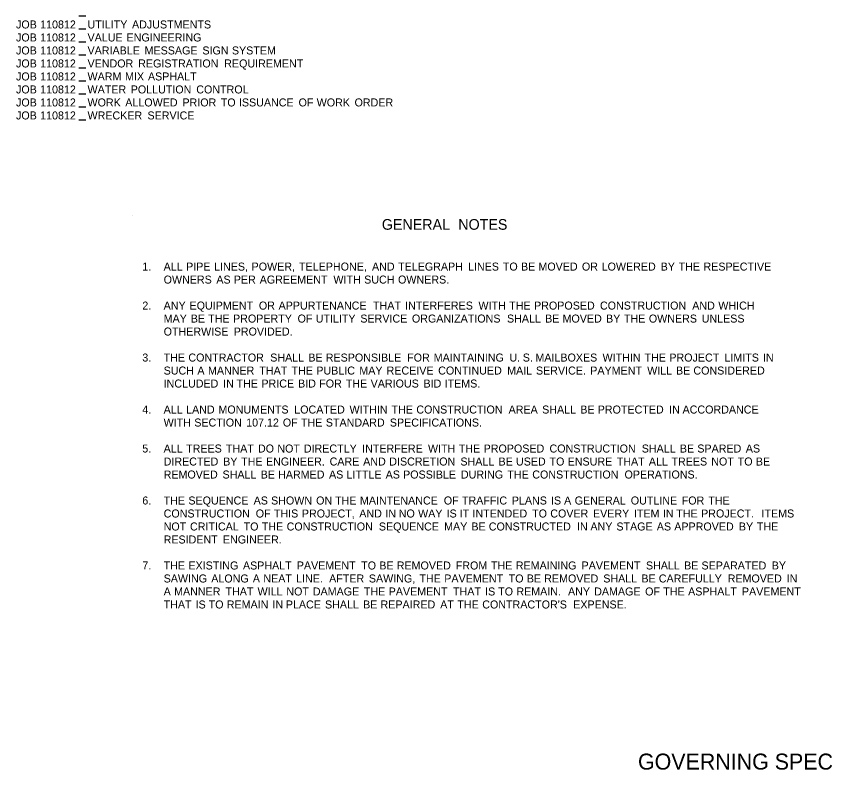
# Model space of a CAD drawing. Extents: x 200 to 2094, y 35 to 1167.
# Drawn here: x 768 to 1375, y 35 to 600 of the extents above; entities that cross this region are included whole.
import ezdxf

# ---------------------------------------------------------------- set-up
doc = ezdxf.new("R2010")
doc.units = 0
doc.layers.add('Default', color=7, linetype='Continuous')
doc.layers.add('R_Annotation', color=7, linetype='Continuous')

msp = doc.modelspace()

# ---------------------------------------------------------------- linework, layer by layer
at = {"layer": 'Default'}
for p, q in [((820.04, 600.08), (814.8, 600.08)), ((820.04, 590.33), (814.8, 590.33)), ((820.04, 580.58), (814.8, 580.58)), ((820.04, 570.83), (814.8, 570.83)), ((820.04, 561.08), (814.8, 561.08)), ((820.04, 551.33), (814.8, 551.33)), ((820.04, 541.58), (814.8, 541.58)), ((820.04, 531.83), (814.8, 531.83)), ((820.04, 522.08), (814.8, 522.08)), ((855.05, 450.43), (855.05, 450.43))]:
    msp.add_line(p, q, dxfattribs=at)

# ---------------------------------------------------------------- texts
for s, height, p in [('JOB', 6, (767.74, 590.87)), (' 110812', 6, (783.6, 590.87)), ('UTILITY', 6, (821.37, 590.87)), (' ADJUSTMENTS', 6, (852.51, 590.87)), ('JOB', 6, (767.74, 581.12)), (' 110812', 6, (783.6, 581.12)), ('VALUE', 6, (821.37, 581.12)), (' ENGINEERING', 6, (848.42, 581.12)), ('JOB', 6, (767.74, 571.37)), (' 110812', 6, (783.6, 571.37)), ('VARIABLE', 6, (821.37, 571.37)), (' MESSAGE', 6, (861.93, 571.37)), (' SIGN', 6, (905.28, 571.37)), (' SYSTEM', 6, (927.42, 571.37)), ('JOB', 6, (767.74, 561.62)), (' 110812', 6, (783.6, 561.62)), ('VENDOR', 6, (821.37, 561.62)), (' REGISTRATION', 6, (857.13, 561.62)), (' REQUIREMENT', 6, (921.65, 561.62)), ('JOB', 6, (767.74, 551.87)), (' 110812', 6, (783.6, 551.87)), ('WARM', 6, (821.37, 551.87)), (' MIX', 6, (847.28, 551.87)), (' ASPHALT', 6, (864.46, 551.87)), ('JOB', 6, (767.74, 542.12)), (' 110812', 6, (783.6, 542.12)), ('WATER', 6, (821.37, 542.12)), (' POLLUTION', 6, (851.53, 542.12)), (' CONTROL', 6, (900.69, 542.12)), ('JOB', 6, (767.74, 532.37)), (' 110812', 6, (783.6, 532.37)), ('WORK', 6, (821.37, 532.37)), (' ALLOWED', 6, (847.43, 532.37)), (' PRIOR', 6, (890.31, 532.37)), (' TO', 6, (919.07, 532.37)), (' ISSUANCE', 6, (932.67, 532.37)), (' OF', 6, (977.41, 532.37)), (' WORK', 6, (991, 532.37)), (' ORDER', 6, (1019.39, 532.37)), ('JOB', 6, (767.74, 522.62)), (' 110812', 6, (783.6, 522.62)), ('WRECKER', 6, (821.37, 522.62)), (' SERVICE', 6, (864.11, 522.62)), ('GENERAL', 8, (1042.08, 439.85)), (' NOTES', 8, (1096.41, 439.85)), ('1.', 6, (862.44, 409.22)), ('ALL', 6, (878.45, 409.22)), (' PIPE', 6, (893.06, 409.22)), (' LINES,', 6, (914.05, 409.22)), (' POWER,', 6, (942.19, 409.22)), (' TELEPHONE,', 6, (977.77, 409.22)), (' AND', 6, (1032.47, 409.22)), (' TELEGRAPH', 6, (1052.05, 409.22)), (' LINES', 6, (1104.49, 409.22)), (' TO', 6, (1130.6, 409.22)), (' BE', 6, (1144.2, 409.22)), (' MOVED', 6, (1157.27, 409.22)), (' OR', 6, (1189.89, 409.22)), (' LOWERED', 6, (1204.68, 409.22)), (' BY', 6, (1248.95, 409.22)), (' THE', 6, (1262.4, 409.22)), (' RESPECTIVE', 6, (1281.05, 409.22)), ('OWNERS', 6, (878.45, 399.47)), (' AS', 6, (915.74, 399.47)), (' PER', 6, (928.81, 399.47)), (' AGREEMENT', 6, (948.27, 399.47)), (' WITH', 6, (1003.53, 399.47)), (' SUCH', 6, (1026.6, 399.47)), (' OWNERS.', 6, (1052.01, 399.47)), ('2.', 6, (862.44, 379.97)), ('ANY', 6, (878.45, 379.97)), (' EQUIPMENT', 6, (895.63, 379.97)), (' OR', 6, (947.63, 379.97)), (' APPURTENANCE', 6, (962.42, 379.97)), (' THAT', 6, (1033.25, 379.97)), (' INTERFERES', 6, (1057.3, 379.97)), (' WITH', 6, (1112.3, 379.97)), (' THE', 6, (1135.36, 379.97)), (' PROPOSED', 6, (1154.01, 379.97)), (' CONSTRUCTION', 6, (1203.42, 379.97)), (' AND', 6, (1272.6, 379.97)), (' WHICH', 6, (1292.18, 379.97)), ('MAY', 6, (878.45, 370.22)), (' BE', 6, (896.55, 370.22)), (' THE', 6, (909.62, 370.22)), (' PROPERTY', 6, (928.27, 370.22)), (' OF', 6, (976.66, 370.22)), (' UTILITY', 6, (990.24, 370.22)), (' SERVICE', 6, (1023.72, 370.22)), (' ORGANIZATIONS', 6, (1062.4, 370.22)), (' SHALL', 6, (1133.7, 370.22)), (' BE', 6, (1162.29, 370.22)), (' MOVED', 6, (1175.36, 370.22)), (' BY', 6, (1207.98, 370.22)), (' THE', 6, (1221.43, 370.22)), (' OWNERS', 6, (1240.08, 370.22)), (' UNLESS', 6, (1279.7, 370.22)), ('OTHERWISE', 6, (878.45, 360.47)), (' PROVIDED.', 6, (928.77, 360.47)), ('3.', 6, (862.44, 340.97)), ('THE', 6, (878.45, 340.97)), (' CONTRACTOR', 6, (894.77, 340.97)), (' SHALL', 6, (956.14, 340.97)), (' BE', 6, (984.73, 340.97)), (' RESPONSIBLE', 6, (997.79, 340.97)), (' FOR', 6, (1058.85, 340.97)), (' MAINTAINING', 6, (1078.76, 340.97)), (' U.', 6, (1135.53, 340.97)), (' S.', 6, (1145.5, 340.97)), (' MAILBOXES', 6, (1155.02, 340.97)), (' WITHIN', 6, (1205.37, 340.97)), (' THE', 6, (1236.81, 340.97)), (' PROJECT', 6, (1255.46, 340.97)), (' LIMITS', 6, (1296.75, 340.97)), (' IN', 6, (1325.65, 340.97)), ('SUCH', 6, (878.45, 331.22)), (' A', 6, (901.53, 331.22)), (' MANNER', 6, (909.46, 331.22)), (' THAT', 6, (948.01, 331.22)), (' THE', 6, (972.06, 331.22)), (' PUBLIC', 6, (990.71, 331.22)), (' MAY', 6, (1022.99, 331.22)), (' RECEIVE', 6, (1043.42, 331.22)), (' CONTINUED', 6, (1082.11, 331.22)), (' MAIL', 6, (1133.83, 331.22)), (' SERVICE.', 6, (1155.42, 331.22)), (' PAYMENT', 6, (1196.16, 331.22)), (' WILL', 6, (1238.85, 331.22)), (' BE', 6, (1260.44, 331.22)), (' CONSIDERED', 6, (1273.5, 331.22)), ('INCLUDED', 6, (878.45, 321.47)), (' IN', 6, (920.86, 321.47)), (' THE', 6, (930.88, 321.47)), (' PRICE', 6, (949.53, 321.47)), (' BID', 6, (977.03, 321.47)), (' FOR', 6, (992.89, 321.47)), (' THE', 6, (1012.8, 321.47)), (' VARIOUS', 6, (1031.45, 321.47)), (' BID', 6, (1071.08, 321.47)), (' ITEMS.', 6, (1086.93, 321.47)), ('4.', 6, (862.44, 301.97)), ('ALL', 6, (878.45, 301.97)), (' LAND', 6, (893.06, 301.97)), (' MONUMENTS', 6, (917.31, 301.97)), (' LOCATED', 6, (974.16, 301.97)), (' WITHIN', 6, (1015.63, 301.97)), (' THE', 6, (1047.08, 301.97)), (' CONSTRUCTION', 6, (1065.72, 301.97)), (' AREA', 6, (1134.9, 301.97)), (' SHALL', 6, (1160.08, 301.97)), (' BE', 6, (1188.67, 301.97)), (' PROTECTED', 6, (1201.74, 301.97)), (' IN', 6, (1255.32, 301.97)), (' ACCORDANCE', 6, (1265.35, 301.97)), ('WITH', 6, (878.45, 292.22)), (' SECTION', 6, (899.19, 292.22)), (' 107.12', 6, (938.1, 292.22)), (' OF', 6, (965.61, 292.22)), (' THE', 6, (979.2, 292.22)), (' STANDARD', 6, (997.85, 292.22)), (' SPECIFICATIONS.', 6, (1045.85, 292.22)), ('5.', 6, (862.44, 272.72)), ('ALL', 6, (878.45, 272.72)), (' TREES', 6, (893.06, 272.72)), (' THAT', 6, (922.91, 272.72)), (' DO', 6, (946.96, 272.72)), (' NOT', 6, (961.49, 272.72)), (' DIRECTLY', 6, (981.35, 272.72)), (' INTERFERE', 6, (1025.07, 272.72)), (' WITH', 6, (1074.46, 272.72)), (' THE', 6, (1097.53, 272.72)), (' PROPOSED', 6, (1116.18, 272.72)), (' CONSTRUCTION', 6, (1165.58, 272.72)), (' SHALL', 6, (1234.76, 272.72)), (' BE', 6, (1263.35, 272.72)), (' SPARED', 6, (1276.42, 272.72)), (' AS', 6, (1312.78, 272.72)), ('DIRECTED', 6, (878.45, 262.97)), (' BY', 6, (920.86, 262.97)), (' THE', 6, (934.31, 262.97)), (' ENGINEER.', 6, (952.95, 262.97)), (' CARE', 6, (1000.67, 262.97)), (' AND', 6, (1025.85, 262.97)), (' DISCRETION', 6, (1045.43, 262.97)), (' SHALL', 6, (1098.78, 262.97)), (' BE', 6, (1127.37, 262.97)), (' USED', 6, (1140.43, 262.97)), (' TO', 6, (1165.61, 262.97)), (' ENSURE', 6, (1179.2, 262.97)), (' THAT', 6, (1216.03, 262.97)), (' ALL', 6, (1240.08, 262.97)), (' TREES', 6, (1257.02, 262.97)), (' NOT', 6, (1286.86, 262.97)), (' TO', 6, (1306.72, 262.97)), (' BE', 6, (1320.32, 262.97)), ('REMOVED', 6, (878.45, 253.22)), (' SHALL', 6, (920.39, 253.22)), (' BE', 6, (948.99, 253.22)), (' HARMED', 6, (962.05, 253.22)), (' AS', 6, (1000.26, 253.22)), (' LITTLE', 6, (1013.34, 253.22)), (' AS', 6, (1042.7, 253.22)), (' POSSIBLE', 6, (1055.78, 253.22)), (' DURING', 6, (1099.13, 253.22)), (' THE', 6, (1134, 253.22)), (' CONSTRUCTION', 6, (1152.65, 253.22)), (' OPERATIONS.', 6, (1221.83, 253.22)), ('6.', 6, (862.44, 233.72)), ('THE', 6, (878.45, 233.72)), (' SEQUENCE', 6, (894.77, 233.72)), (' AS', 6, (943.71, 233.72)), (' SHOWN', 6, (956.78, 233.72)), (' ON', 6, (990.56, 233.72)), (' THE', 6, (1004.78, 233.72)), (' MAINTENANCE', 6, (1023.43, 233.72)), (' OF', 6, (1086.33, 233.72)), (' TRAFFIC', 6, (1099.92, 233.72)), (' PLANS', 6, (1137.31, 233.72)), (' IS', 6, (1166.69, 233.72)), (' A', 6, (1176.5, 233.72)), (' GENERAL', 6, (1184.44, 233.72)), (' OUTLINE', 6, (1226.54, 233.72)), (' FOR', 6, (1264.75, 233.72)), (' THE', 6, (1284.66, 233.72)), ('CONSTRUCTION', 6, (878.45, 223.97)), (' OF', 6, (945.3, 223.97)), (' THIS', 6, (958.89, 223.97)), (' PROJECT,', 6, (979.87, 223.97)), (' AND', 6, (1022.92, 223.97)), (' IN', 6, (1042.5, 223.97)), (' NO', 6, (1052.52, 223.97)), (' WAY', 6, (1067.05, 223.97)), (' IS', 6, (1088.41, 223.97)), (' IT', 6, (1098.22, 223.97)), (' INTENDED', 6, (1107.83, 223.97)), (' TO', 6, (1152.56, 223.97)), (' COVER', 6, (1166.16, 223.97)), (' EVERY', 6, (1198.19, 223.97)), (' ITEM', 6, (1228.88, 223.97)), (' IN', 6, (1250.6, 223.97)), (' THE', 6, (1260.63, 223.97)), (' PROJECT.', 6, (1279.28, 223.97)), ('  ITEMS', 6, (1322.33, 223.97)), ('NOT', 6, (878.45, 214.22)), (' CRITICAL', 6, (895.98, 214.22)), (' TO', 6, (936.2, 214.22)), (' THE', 6, (949.8, 214.22)), (' CONSTRUCTION', 6, (968.45, 214.22)), (' SEQUENCE', 6, (1037.63, 214.22)), (' MAY', 6, (1086.56, 214.22)), (' BE', 6, (1107, 214.22)), (' CONSTRUCTED', 6, (1120.06, 214.22)), (' IN', 6, (1186.22, 214.22)), (' ANY', 6, (1196.25, 214.22)), (' STAGE', 6, (1215.75, 214.22)), (' AS', 6, (1246.05, 214.22)), (' APPROVED', 6, (1259.13, 214.22)), (' BY', 6, (1307.6, 214.22)), (' THE', 6, (1321.05, 214.22)), ('RESIDENT', 6, (878.45, 204.47)), (' ENGINEER.', 6, (920.67, 204.47)), ('7.', 6, (862.44, 184.97)), ('THE', 6, (878.45, 184.97)), (' EXISTING', 6, (894.77, 184.97)), (' ASPHALT', 6, (935.7, 184.97)), (' PAVEMENT', 6, (976.07, 184.97)), (' TO', 6, (1024.36, 184.97)), (' BE', 6, (1037.95, 184.97)), (' REMOVED', 6, (1051.02, 184.97)), (' FROM', 6, (1095.29, 184.97)), (' THE', 6, (1121.67, 184.97)), (' REMAINING', 6, (1140.32, 184.97)), (' PAVEMENT', 6, (1189.63, 184.97)), (' SHALL', 6, (1237.91, 184.97)), (' BE', 6, (1266.51, 184.97)), (' SEPARATED', 6, (1279.57, 184.97)), (' BY', 6, (1332.24, 184.97)), ('SAWING', 6, (878.45, 175.22)), (' ALONG', 6, (911.92, 175.22)), (' A', 6, (943.08, 175.22)), (' NEAT', 6, (951.01, 175.22)), (' LINE.', 6, (975.53, 175.22)), ('  AFTER', 6, (998.09, 175.22)), (' SAWING,', 6, (1030.12, 175.22)), (' THE', 6, (1068.03, 175.22)), (' PAVEMENT', 6, (1086.68, 175.22)), (' TO', 6, (1134.96, 175.22)), (' BE', 6, (1148.56, 175.22)), (' REMOVED', 6, (1161.62, 175.22)), (' SHALL', 6, (1205.9, 175.22)), (' BE', 6, (1234.49, 175.22)), (' CAREFULLY', 6, (1247.55, 175.22)), (' REMOVED', 6, (1299.2, 175.22)), (' IN', 6, (1343.48, 175.22)), ('A', 6, (878.45, 165.47)), (' MANNER', 6, (884.06, 165.47)), (' THAT', 6, (922.6, 165.47)), (' WILL', 6, (946.65, 165.47)), (' NOT', 6, (968.24, 165.47)), (' DAMAGE', 6, (988.1, 165.47)), (' THE', 6, (1026.32, 165.47)), (' PAVEMENT', 6, (1044.97, 165.47)), (' THAT', 6, (1093.25, 165.47)), (' IS', 6, (1117.3, 165.47)), (' TO', 6, (1127.11, 165.47)), (' REMAIN.', 6, (1140.71, 165.47)), ('  ANY', 6, (1177.24, 165.47)), (' DAMAGE', 6, (1199.07, 165.47)), (' OF', 6, (1237.29, 165.47)), (' THE', 6, (1250.87, 165.47)), (' ASPHALT', 6, (1269.52, 165.47)), (' PAVEMENT', 6, (1309.89, 165.47)), ('THAT', 6, (878.45, 155.72)), (' IS', 6, (900.17, 155.72)), (' TO', 6, (909.98, 155.72)), (' REMAIN', 6, (923.58, 155.72)), (' IN', 6, (957.83, 155.72)), (' PLACE', 6, (967.85, 155.72)), (' SHALL', 6, (997.22, 155.72)), (' BE', 6, (1025.81, 155.72)), (' REPAIRED', 6, (1038.88, 155.72)), (' AT', 6, (1083.62, 155.72)), (' THE', 6, (1096.5, 155.72)), (" CONTRACTOR'S", 6, (1115.15, 155.72)), (' EXPENSE.', 6, (1183.38, 155.72))]:
    msp.add_text(s, height=height, dxfattribs=at).set_placement(p)
at = {"layer": 'R_Annotation'}
msp.add_text('GOVERNING SPECIFICATIONS & GENERAL NOTES', height=12, rotation=360, dxfattribs=at).set_placement((1234.17, 34.84))

doc.saveas('drawing.dxf')
